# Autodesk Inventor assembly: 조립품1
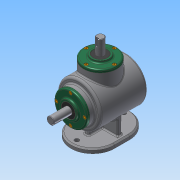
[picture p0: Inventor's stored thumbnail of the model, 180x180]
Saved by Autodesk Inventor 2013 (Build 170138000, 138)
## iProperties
Created: 2016-04
Part Number: 조립품1
Document SubType Name: Assembly
Designer: Administrator
Author: Administrator
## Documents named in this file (14)
- C:\Users\Administrator\Desktop\460407V1007\조립품1.iam
- C:\Users\Administrator\Desktop\460407V1007\M4.ipt
- C:\Users\Administrator\Desktop\460407V1007\메인 베벨기어.ipt
- C:\Users\Administrator\Desktop\460407V1007\메인 축.ipt
- 메인 축.ipt
- C:\Users\Administrator\Desktop\460407V1007\베어링 6203.ipt
- C:\Users\Administrator\Desktop\460407V1007\본체.ipt
- C:\Users\Administrator\Desktop\460407V1007\서브 베벨기어.ipt
- C:\Users\Administrator\Desktop\460407V1007\서브 축.ipt
- 서브 축.ipt
- C:\Users\Administrator\Desktop\460407V1007\오일실 17 32 8.ipt
- C:\Users\Administrator\Desktop\460407V1007\커버.ipt
- C:\Users\Administrator\Desktop\460407V1007\키 4x4.ipt
- C:\Users\Administrator\Desktop\460407V1007\키 5x5.ipt
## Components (8 placed, 1 different names)
1. M4:2
2. M4:3
3. M4:4
4. M4:5
5. M4:1
6. M4:6
7. M4:7
8. M4:8
